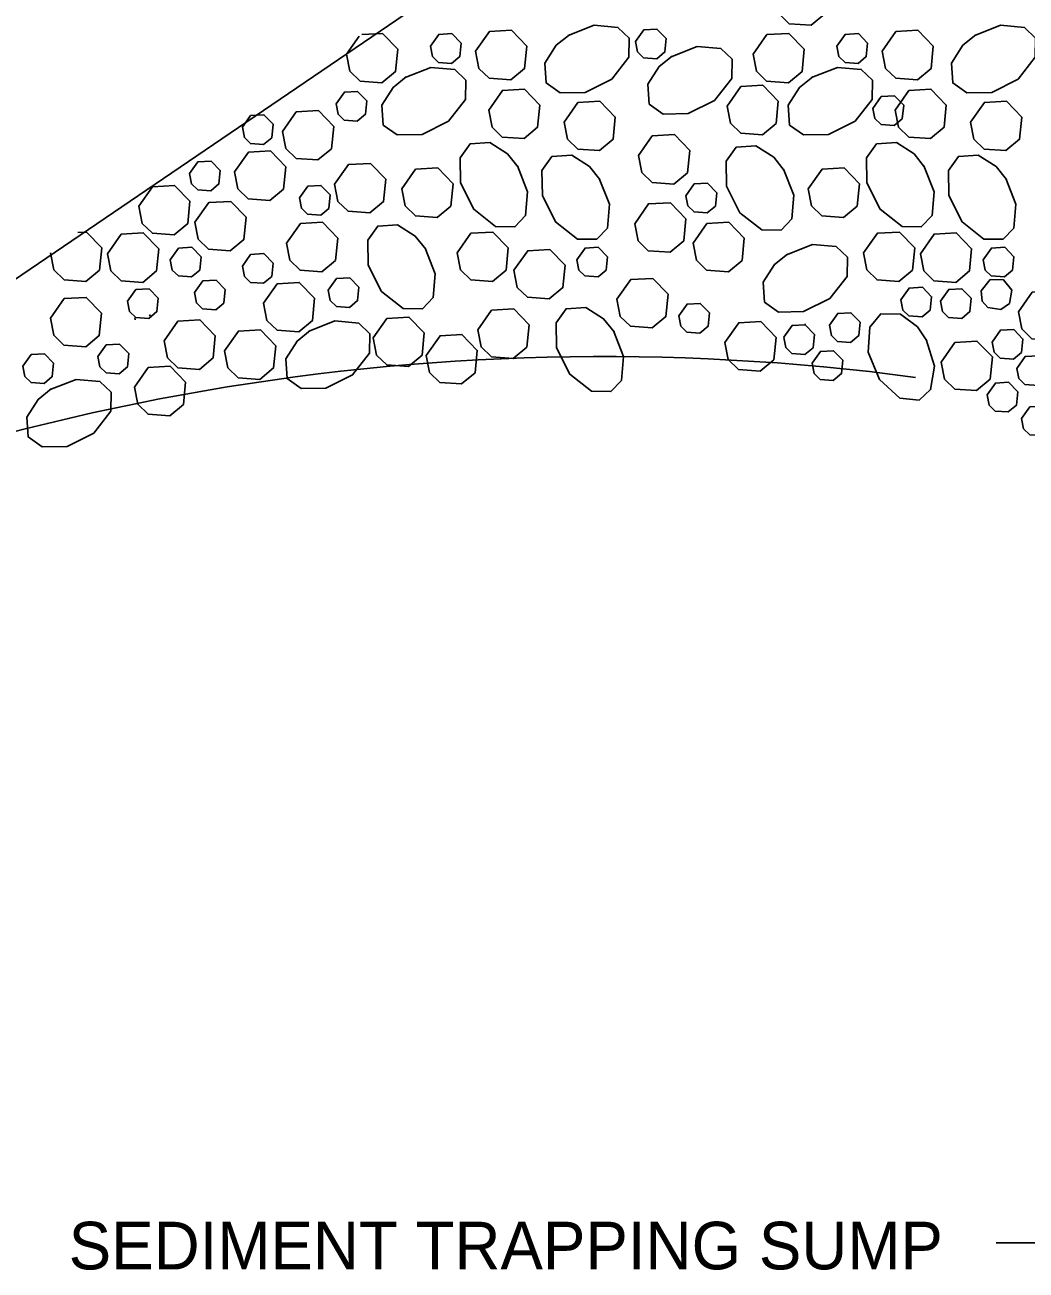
# Model space of a CAD drawing. Extents: x 6709491 to 6710959, y 1869789 to 1870763.
# Drawn here: x 6709570.8 to 6709696.9, y 1870141.6 to 1870298.5 of the extents above; entities that cross this region are included whole.
import ezdxf

# ---------------------------------------------------------------- set-up
doc = ezdxf.new("R2010")
doc.units = 0
for name, color, linetype in [('56 Stg 3 Anno', 7, 'Continuous'), ('57 Undefined', 7, 'Continuous'), ('60 Nongeo Data', 7, 'Continuous')]:
    doc.layers.add(name, color=color, linetype=linetype)

msp = doc.modelspace()

# ---------------------------------------------------------------- linework, layer by layer
at = {"layer": '56 Stg 3 Anno'}
msp.add_line((6709713.58, 1870145.05), (6709693.08, 1870145.05), dxfattribs=at)
at = {"layer": '60 Nongeo Data'}
msp.add_line((6709495.94, 1870216.26), (6709884.38, 1870481.01), dxfattribs=at)
for points in [[(6709665.33, 1870302.03), (6709667.07, 1870304.51), (6709669.85, 1870304.67), (6709671.78, 1870302.66), (6709671.5, 1870299.86), (6709669.79, 1870298.43), (6709667.04, 1870298.63), (6709665.75, 1870299.88), (6709665.34, 1870302.03)], [(6709613.19, 1870297.27), (6709615.8, 1870297.42), (6709617.74, 1870295.42), (6709617.46, 1870292.61), (6709615.74, 1870291.19), (6709613, 1870291.39), (6709611.71, 1870292.64), (6709611.29, 1870294.79)], [(6709611.29, 1870294.79), (6709612.88, 1870297.05)], [(6709612.88, 1870297.05), (6709612.88, 1870297.06)], [(6709621.84, 1870295.8), (6709622.89, 1870297.29), (6709624.55, 1870297.38), (6709625.71, 1870296.18), (6709625.54, 1870294.5), (6709624.51, 1870293.64), (6709622.87, 1870293.76), (6709622.09, 1870294.51), (6709621.84, 1870295.8)], [(6709627.54, 1870295.16), (6709629.28, 1870297.64), (6709632.06, 1870297.8), (6709633.99, 1870295.79), (6709633.71, 1870292.99), (6709631.99, 1870291.56), (6709629.25, 1870291.76), (6709627.96, 1870293.01), (6709627.54, 1870295.16)], [(6709639.21, 1870297.14), (6709642.47, 1870298.43), (6709645.46, 1870298.17), (6709646.88, 1870296.82), (6709646.83, 1870294.4), (6709644.68, 1870291.64), (6709641.34, 1870289.97), (6709638.2, 1870289.92), (6709636.44, 1870291.18), (6709636.27, 1870293.68), (6709637.7, 1870295.91), (6709639.35, 1870297.23)], [(6709647.67, 1870296.38), (6709648.71, 1870297.86), (6709650.38, 1870297.95), (6709651.54, 1870296.75), (6709651.37, 1870295.07), (6709650.34, 1870294.22), (6709648.7, 1870294.33), (6709647.92, 1870295.09), (6709647.67, 1870296.38)], [(6709662.48, 1870294.79), (6709664.22, 1870297.26), (6709667, 1870297.42), (6709668.93, 1870295.42), (6709668.65, 1870292.61), (6709666.93, 1870291.19), (6709664.19, 1870291.39), (6709662.9, 1870292.64), (6709662.48, 1870294.79)], [(6709673.03, 1870295.8), (6709674.08, 1870297.29), (6709675.74, 1870297.38), (6709676.9, 1870296.18), (6709676.74, 1870294.5), (6709675.71, 1870293.64), (6709674.06, 1870293.76), (6709673.29, 1870294.51), (6709673.04, 1870295.8)], [(6709678.74, 1870295.16), (6709680.47, 1870297.64), (6709683.25, 1870297.8), (6709685.18, 1870295.79), (6709684.9, 1870292.99), (6709683.19, 1870291.56), (6709680.45, 1870291.76), (6709679.15, 1870293.01), (6709678.74, 1870295.16)], [(6709690.41, 1870297.14), (6709693.66, 1870298.43), (6709696.65, 1870298.17), (6709698.07, 1870296.82), (6709698.03, 1870294.4), (6709695.87, 1870291.64), (6709692.54, 1870289.97), (6709689.4, 1870289.92), (6709687.63, 1870291.18), (6709687.46, 1870293.68), (6709688.9, 1870295.91), (6709690.54, 1870297.23)], [(6709652.18, 1870294.47), (6709655.43, 1870295.76), (6709658.42, 1870295.5), (6709659.84, 1870294.15), (6709659.79, 1870291.73), (6709657.64, 1870288.97), (6709654.31, 1870287.3), (6709651.17, 1870287.25), (6709649.4, 1870288.51), (6709649.23, 1870291.01), (6709650.67, 1870293.24), (6709652.31, 1870294.55)], [(6709618.66, 1870291.84), (6709621.91, 1870293.13), (6709624.9, 1870292.87), (6709626.32, 1870291.52), (6709626.28, 1870289.1), (6709624.12, 1870286.34), (6709620.79, 1870284.67), (6709617.65, 1870284.62), (6709615.88, 1870285.87), (6709615.71, 1870288.38), (6709617.15, 1870290.61), (6709618.79, 1870291.92)], [(6709669.85, 1870291.84), (6709673.11, 1870293.13), (6709676.1, 1870292.87), (6709677.52, 1870291.52), (6709677.47, 1870289.1), (6709675.32, 1870286.34), (6709671.98, 1870284.67), (6709668.84, 1870284.62), (6709667.08, 1870285.87), (6709666.91, 1870288.38), (6709668.34, 1870290.61), (6709669.99, 1870291.92)], [(6709659.21, 1870288.24), (6709660.95, 1870290.72), (6709663.73, 1870290.88), (6709665.66, 1870288.87), (6709665.38, 1870286.07), (6709663.66, 1870284.64), (6709660.92, 1870284.84), (6709659.63, 1870286.09), (6709659.21, 1870288.24)], [(6709609.96, 1870288.52), (6709611.01, 1870290.01), (6709612.67, 1870290.1), (6709613.83, 1870288.9), (6709613.66, 1870287.22), (6709612.63, 1870286.36), (6709610.99, 1870286.48), (6709610.21, 1870287.23), (6709609.96, 1870288.52)], [(6709629.18, 1870287.76), (6709630.92, 1870290.23), (6709633.69, 1870290.39), (6709635.62, 1870288.39), (6709635.35, 1870285.58), (6709633.63, 1870284.16), (6709630.89, 1870284.35), (6709629.6, 1870285.61), (6709629.18, 1870287.76)], [(6709677.58, 1870287.97), (6709678.62, 1870289.45), (6709680.29, 1870289.55), (6709681.45, 1870288.35), (6709681.28, 1870286.66), (6709680.25, 1870285.81), (6709678.61, 1870285.93), (6709677.83, 1870286.68), (6709677.58, 1870287.97)], [(6709680.37, 1870287.76), (6709682.11, 1870290.23), (6709684.89, 1870290.39), (6709686.82, 1870288.39), (6709686.54, 1870285.58), (6709684.82, 1870284.16), (6709682.08, 1870284.35), (6709680.79, 1870285.61), (6709680.37, 1870287.76)], [(6709603.21, 1870285.07), (6709604.95, 1870287.54), (6709607.73, 1870287.7), (6709609.66, 1870285.7), (6709609.38, 1870282.89), (6709607.67, 1870281.47), (6709604.92, 1870281.67), (6709603.63, 1870282.92), (6709603.22, 1870285.07)], [(6709638.69, 1870286.24), (6709640.43, 1870288.72), (6709643.2, 1870288.87), (6709645.13, 1870286.87), (6709644.85, 1870284.07), (6709643.14, 1870282.64), (6709640.4, 1870282.84), (6709639.11, 1870284.09), (6709638.69, 1870286.24)], [(6709689.88, 1870286.24), (6709691.62, 1870288.72), (6709694.4, 1870288.87), (6709696.33, 1870286.87), (6709696.05, 1870284.07), (6709694.33, 1870282.64), (6709691.59, 1870282.84), (6709690.3, 1870284.09), (6709689.88, 1870286.24)], [(6709598.16, 1870285.58), (6709599.2, 1870287.06), (6709600.87, 1870287.16), (6709602.03, 1870285.96), (6709601.86, 1870284.27), (6709600.83, 1870283.42), (6709599.18, 1870283.54), (6709598.41, 1870284.29), (6709598.16, 1870285.58)], [(6709648.05, 1870282.03), (6709649.79, 1870284.51), (6709652.57, 1870284.67), (6709654.5, 1870282.66), (6709654.22, 1870279.86), (6709652.51, 1870278.43), (6709649.77, 1870278.63), (6709648.48, 1870279.88), (6709648.06, 1870282.03)], [(6709632.8, 1870280.71), (6709634.09, 1870277.45), (6709633.83, 1870274.46), (6709632.48, 1870273.04), (6709630.05, 1870273.09), (6709627.3, 1870275.25), (6709625.63, 1870278.58), (6709625.58, 1870281.72), (6709626.83, 1870283.49), (6709629.33, 1870283.65), (6709631.57, 1870282.22), (6709632.88, 1870280.58)], [(6709666.31, 1870280.29), (6709667.6, 1870277.03), (6709667.35, 1870274.04), (6709666, 1870272.62), (6709663.57, 1870272.67), (6709660.81, 1870274.82), (6709659.15, 1870278.16), (6709659.09, 1870281.3), (6709660.35, 1870283.06), (6709662.85, 1870283.23), (6709665.09, 1870281.8), (6709666.4, 1870280.15)], [(6709683.99, 1870280.71), (6709685.28, 1870277.45), (6709685.02, 1870274.46), (6709683.67, 1870273.04), (6709681.25, 1870273.09), (6709678.49, 1870275.25), (6709676.83, 1870278.58), (6709676.77, 1870281.72), (6709678.03, 1870283.49), (6709680.53, 1870283.65), (6709682.76, 1870282.22), (6709684.07, 1870280.58)], [(6709591.5, 1870279.75), (6709592.54, 1870281.23), (6709594.21, 1870281.33), (6709595.37, 1870280.13), (6709595.2, 1870278.44), (6709594.17, 1870277.59), (6709592.53, 1870277.71), (6709591.75, 1870278.46), (6709591.5, 1870279.75)], [(6709597.18, 1870279.97), (6709598.92, 1870282.44), (6709601.7, 1870282.6), (6709603.63, 1870280.6), (6709603.35, 1870277.79), (6709601.63, 1870276.37), (6709598.89, 1870276.57), (6709597.6, 1870277.82), (6709597.18, 1870279.97)], [(6709643.11, 1870279.13), (6709644.4, 1870275.88), (6709644.14, 1870272.89), (6709642.79, 1870271.47), (6709640.37, 1870271.51), (6709637.61, 1870273.67), (6709635.94, 1870277), (6709635.89, 1870280.14), (6709637.14, 1870281.91), (6709639.65, 1870282.07), (6709641.88, 1870280.64), (6709643.19, 1870279)], [(6709694.3, 1870279.13), (6709695.59, 1870275.88), (6709695.34, 1870272.89), (6709693.98, 1870271.47), (6709691.56, 1870271.51), (6709688.8, 1870273.67), (6709687.14, 1870277), (6709687.08, 1870280.14), (6709688.34, 1870281.91), (6709690.84, 1870282.07), (6709693.08, 1870280.64), (6709694.39, 1870279)], [(6709609.77, 1870278.41), (6709611.51, 1870280.88), (6709614.29, 1870281.04), (6709616.22, 1870279.04), (6709615.94, 1870276.23), (6709614.22, 1870274.8), (6709611.48, 1870275), (6709610.19, 1870276.25), (6709609.77, 1870278.4)], [(6709618.24, 1870277.83), (6709619.98, 1870280.3), (6709622.76, 1870280.46), (6709624.69, 1870278.46), (6709624.41, 1870275.65), (6709622.7, 1870274.23), (6709619.96, 1870274.42), (6709618.67, 1870275.67), (6709618.25, 1870277.83)], [(6709669.44, 1870277.83), (6709671.18, 1870280.3), (6709673.95, 1870280.46), (6709675.89, 1870278.46), (6709675.61, 1870275.65), (6709673.89, 1870274.23), (6709671.15, 1870274.42), (6709669.86, 1870275.67), (6709669.44, 1870277.83)], [(6709585.11, 1870275.63), (6709586.85, 1870278.1), (6709589.62, 1870278.26), (6709591.56, 1870276.26), (6709591.28, 1870273.45), (6709589.56, 1870272.03), (6709586.82, 1870272.23), (6709585.53, 1870273.48), (6709585.11, 1870275.63)], [(6709605.35, 1870276.68), (6709606.39, 1870278.16), (6709608.06, 1870278.26), (6709609.21, 1870277.06), (6709609.05, 1870275.37), (6709608.02, 1870274.52), (6709606.37, 1870274.64), (6709605.6, 1870275.39), (6709605.35, 1870276.68)], [(6709654.03, 1870276.96), (6709655.08, 1870278.45), (6709656.74, 1870278.54), (6709657.9, 1870277.34), (6709657.73, 1870275.66), (6709656.7, 1870274.8), (6709655.06, 1870274.92), (6709654.28, 1870275.67), (6709654.03, 1870276.96)], [(6709592.19, 1870273.62), (6709593.93, 1870276.09), (6709596.7, 1870276.25), (6709598.63, 1870274.25), (6709598.35, 1870271.44), (6709596.64, 1870270.02), (6709593.9, 1870270.22), (6709592.61, 1870271.47), (6709592.19, 1870273.62)], [(6709647.57, 1870273.44), (6709649.31, 1870275.92), (6709652.08, 1870276.08), (6709654.01, 1870274.07), (6709653.74, 1870271.27), (6709652.02, 1870269.84), (6709649.28, 1870270.04), (6709647.99, 1870271.29), (6709647.57, 1870273.44)], [(6709603.72, 1870270.99), (6709605.46, 1870273.46), (6709608.24, 1870273.62), (6709610.17, 1870271.62), (6709609.89, 1870268.81), (6709608.18, 1870267.38), (6709605.43, 1870267.58), (6709604.14, 1870268.83), (6709603.73, 1870270.98)], [(6709654.92, 1870270.99), (6709656.66, 1870273.46), (6709659.43, 1870273.62), (6709661.37, 1870271.62), (6709661.09, 1870268.81), (6709659.37, 1870267.38), (6709656.63, 1870267.58), (6709655.34, 1870268.83), (6709654.92, 1870270.98)], [(6709577.42, 1870272.33), (6709578.53, 1870272.39), (6709580.46, 1870270.39), (6709580.18, 1870267.59), (6709578.46, 1870266.16), (6709575.72, 1870266.36), (6709574.43, 1870267.61), (6709574.01, 1870269.76)], [(6709581.17, 1870269.65), (6709582.91, 1870272.13), (6709585.68, 1870272.29), (6709587.62, 1870270.28), (6709587.34, 1870267.48), (6709585.62, 1870266.05), (6709582.88, 1870266.25), (6709581.59, 1870267.5), (6709581.17, 1870269.65)], [(6709621.17, 1870270.36), (6709622.46, 1870267.11), (6709622.2, 1870264.12), (6709620.85, 1870262.7), (6709618.43, 1870262.74), (6709615.67, 1870264.9), (6709614.01, 1870268.23), (6709613.95, 1870271.37), (6709615.21, 1870273.14), (6709617.71, 1870273.31), (6709619.94, 1870271.87), (6709621.25, 1870270.23)], [(6709625.21, 1870269.76), (6709626.94, 1870272.23), (6709629.72, 1870272.39), (6709631.65, 1870270.39), (6709631.37, 1870267.59), (6709629.66, 1870266.16), (6709626.92, 1870266.36), (6709625.63, 1870267.61), (6709625.21, 1870269.76)], [(6709676.4, 1870269.76), (6709678.14, 1870272.23), (6709680.92, 1870272.39), (6709682.85, 1870270.39), (6709682.57, 1870267.59), (6709680.85, 1870266.16), (6709678.11, 1870266.36), (6709676.82, 1870267.61), (6709676.4, 1870269.76)], [(6709683.55, 1870269.65), (6709685.29, 1870272.13), (6709688.07, 1870272.29), (6709690, 1870270.28), (6709689.72, 1870267.48), (6709688.01, 1870266.05), (6709685.26, 1870266.25), (6709683.97, 1870267.5), (6709683.56, 1870269.65)], [(6709589.08, 1870268.89), (6709590.12, 1870270.37), (6709591.79, 1870270.47), (6709592.95, 1870269.27), (6709592.78, 1870267.59), (6709591.75, 1870266.73), (6709590.11, 1870266.85), (6709589.33, 1870267.6), (6709589.08, 1870268.89)], [(6709640.28, 1870268.89), (6709641.32, 1870270.37), (6709642.99, 1870270.47), (6709644.14, 1870269.27), (6709643.98, 1870267.59), (6709642.95, 1870266.73), (6709641.3, 1870266.85), (6709640.53, 1870267.6), (6709640.28, 1870268.89)], [(6709666.7, 1870269.53), (6709669.95, 1870270.82), (6709672.94, 1870270.56), (6709674.36, 1870269.21), (6709674.32, 1870266.79), (6709672.16, 1870264.03), (6709668.83, 1870262.37), (6709665.69, 1870262.31), (6709663.92, 1870263.57), (6709663.75, 1870266.07), (6709665.19, 1870268.31), (6709666.83, 1870269.62)], [(6709691.47, 1870268.89), (6709692.51, 1870270.37), (6709694.18, 1870270.47), (6709695.34, 1870269.27), (6709695.17, 1870267.59), (6709694.14, 1870266.73), (6709692.49, 1870266.85), (6709691.72, 1870267.6), (6709691.47, 1870268.89)], [(6709598.16, 1870268.09), (6709599.2, 1870269.57), (6709600.87, 1870269.67), (6709602.03, 1870268.47), (6709601.86, 1870266.79), (6709600.83, 1870265.93), (6709599.18, 1870266.05), (6709598.41, 1870266.8), (6709598.16, 1870268.09)], [(6709632.36, 1870267.57), (6709634.1, 1870270.04), (6709636.88, 1870270.2), (6709638.81, 1870268.2), (6709638.53, 1870265.4), (6709636.81, 1870263.97), (6709634.07, 1870264.17), (6709632.78, 1870265.42), (6709632.36, 1870267.57)], [(6709592.13, 1870264.75), (6709593.17, 1870266.23), (6709594.84, 1870266.33), (6709595.99, 1870265.13), (6709595.83, 1870263.44), (6709594.8, 1870262.59), (6709593.15, 1870262.71), (6709592.38, 1870263.46), (6709592.13, 1870264.75)], [(6709600.81, 1870263.41), (6709602.55, 1870265.88), (6709605.32, 1870266.04), (6709607.26, 1870264.04), (6709606.98, 1870261.23), (6709605.26, 1870259.81), (6709602.52, 1870260.01), (6709601.23, 1870261.26), (6709600.81, 1870263.41)], [(6709608.97, 1870265.05), (6709610.02, 1870266.54), (6709611.68, 1870266.63), (6709612.84, 1870265.43), (6709612.67, 1870263.75), (6709611.64, 1870262.89), (6709610, 1870263.01), (6709609.22, 1870263.76), (6709608.97, 1870265.05)], [(6709645.33, 1870263.91), (6709647.07, 1870266.39), (6709649.85, 1870266.55), (6709651.78, 1870264.55), (6709651.5, 1870261.74), (6709649.78, 1870260.31), (6709647.04, 1870260.51), (6709645.75, 1870261.76), (6709645.33, 1870263.91)], [(6709691.2, 1870264.99), (6709692.36, 1870266.39), (6709694.03, 1870266.36), (6709695.09, 1870265.07), (6709694.79, 1870263.4), (6709693.7, 1870262.63), (6709692.07, 1870262.88), (6709691.35, 1870263.68), (6709691.2, 1870264.99)], [(6709573.98, 1870261.53), (6709575.72, 1870264), (6709578.49, 1870264.16), (6709580.42, 1870262.16), (6709580.14, 1870259.35), (6709578.43, 1870257.93), (6709575.69, 1870258.13), (6709574.4, 1870259.38), (6709573.98, 1870261.53)], [(6709583.7, 1870263.67), (6709584.74, 1870265.15), (6709586.41, 1870265.25), (6709587.57, 1870264.05), (6709587.4, 1870262.37), (6709586.37, 1870261.51), (6709584.72, 1870261.63), (6709583.95, 1870262.38), (6709583.7, 1870263.67)], [(6709681.09, 1870263.85), (6709682.13, 1870265.33), (6709683.8, 1870265.43), (6709684.96, 1870264.23), (6709684.79, 1870262.55), (6709683.76, 1870261.69), (6709682.11, 1870261.81), (6709681.34, 1870262.56), (6709681.09, 1870263.85)], [(6709686.08, 1870263.67), (6709687.13, 1870265.15), (6709688.79, 1870265.25), (6709689.95, 1870264.05), (6709689.79, 1870262.37), (6709688.76, 1870261.51), (6709687.11, 1870261.63), (6709686.34, 1870262.38), (6709686.09, 1870263.67)], [(6709695.9, 1870262.34), (6709697.64, 1870264.82), (6709700.41, 1870264.98), (6709702.34, 1870262.98), (6709702.06, 1870260.17), (6709700.35, 1870258.74), (6709697.61, 1870258.94), (6709696.32, 1870260.19), (6709695.9, 1870262.34)], [(6709627.81, 1870260.07), (6709629.55, 1870262.54), (6709632.33, 1870262.7), (6709634.26, 1870260.7), (6709633.98, 1870257.9), (6709632.26, 1870256.47), (6709629.52, 1870256.67), (6709628.23, 1870257.92), (6709627.81, 1870260.07)], [(6709644.89, 1870259.94), (6709646.18, 1870256.69), (6709645.92, 1870253.7), (6709644.57, 1870252.28), (6709642.14, 1870252.33), (6709639.39, 1870254.48), (6709637.72, 1870257.81), (6709637.67, 1870260.95), (6709638.92, 1870262.72), (6709641.42, 1870262.89), (6709643.66, 1870261.46), (6709644.97, 1870259.81)], [(6709653.12, 1870261.82), (6709654.16, 1870263.31), (6709655.83, 1870263.4), (6709656.99, 1870262.2), (6709656.82, 1870260.52), (6709655.79, 1870259.66), (6709654.14, 1870259.78), (6709653.37, 1870260.53), (6709653.12, 1870261.82)], [(6709584.66, 1870261.33), (6709584.61, 1870261.59)], [(6709586.44, 1870261.83), (6709586.57, 1870261.94)], [(6709588.3, 1870258.69), (6709590.04, 1870261.17), (6709592.82, 1870261.33), (6709594.75, 1870259.32), (6709594.47, 1870256.52), (6709592.75, 1870255.09), (6709590.01, 1870255.29), (6709588.72, 1870256.54), (6709588.3, 1870258.69)], [(6709606.56, 1870259.89), (6709609.82, 1870261.18), (6709612.81, 1870260.92), (6709614.23, 1870259.57), (6709614.18, 1870257.14), (6709612.03, 1870254.38), (6709608.69, 1870252.72), (6709605.55, 1870252.66), (6709603.79, 1870253.92), (6709603.62, 1870256.42), (6709605.05, 1870258.66), (6709606.7, 1870259.97)], [(6709614.63, 1870259.04), (6709616.36, 1870261.51), (6709619.14, 1870261.67), (6709621.07, 1870259.67), (6709620.79, 1870256.87), (6709619.08, 1870255.44), (6709616.34, 1870255.64), (6709615.05, 1870256.89), (6709614.63, 1870259.04)], [(6709658.93, 1870258.47), (6709660.67, 1870260.95), (6709663.45, 1870261.11), (6709665.38, 1870259.1), (6709665.1, 1870256.3), (6709663.38, 1870254.87), (6709660.64, 1870255.07), (6709659.35, 1870256.32), (6709658.93, 1870258.47)], [(6709669.05, 1870260.78), (6709669.04, 1870260.82)], [(6709672.1, 1870260.64), (6709673.14, 1870262.13), (6709674.81, 1870262.22), (6709675.97, 1870261.02), (6709675.8, 1870259.34), (6709674.77, 1870258.48), (6709673.13, 1870258.6), (6709672.35, 1870259.35), (6709672.1, 1870260.64)], [(6709684.3, 1870258.84), (6709685.33, 1870255.5), (6709684.84, 1870252.54), (6709683.39, 1870251.22), (6709680.97, 1870251.46), (6709678.39, 1870253.82), (6709676.99, 1870257.27), (6709677.18, 1870260.41), (6709678.57, 1870262.07), (6709681.07, 1870262.05), (6709683.19, 1870260.44), (6709684.37, 1870258.7)], [(6709595.92, 1870257.43), (6709597.66, 1870259.9), (6709600.44, 1870260.06), (6709602.37, 1870258.06), (6709602.09, 1870255.26), (6709600.37, 1870253.83), (6709597.63, 1870254.03), (6709596.34, 1870255.28), (6709595.92, 1870257.43)], [(6709621.31, 1870256.85), (6709623.05, 1870259.32), (6709625.82, 1870259.48), (6709627.75, 1870257.48), (6709627.47, 1870254.67), (6709625.76, 1870253.25), (6709623.02, 1870253.44), (6709621.73, 1870254.7), (6709621.31, 1870256.85)], [(6709666.34, 1870259.13), (6709667.39, 1870260.61), (6709669.05, 1870260.71), (6709670.21, 1870259.5), (6709670.05, 1870257.82), (6709669.02, 1870256.96), (6709667.37, 1870257.08), (6709666.6, 1870257.83), (6709666.35, 1870259.12)], [(6709692.6, 1870258.53), (6709693.64, 1870260.02), (6709695.31, 1870260.11), (6709696.47, 1870258.91), (6709696.3, 1870257.23), (6709695.27, 1870256.37), (6709693.62, 1870256.49), (6709692.85, 1870257.24), (6709692.6, 1870258.53)], [(6709579.97, 1870256.7), (6709581.01, 1870258.18), (6709582.68, 1870258.28), (6709583.84, 1870257.08), (6709583.67, 1870255.39), (6709582.64, 1870254.54), (6709581, 1870254.66), (6709580.22, 1870255.41), (6709579.97, 1870256.7)], [(6709686.17, 1870256.01), (6709687.91, 1870258.49), (6709690.68, 1870258.65), (6709692.62, 1870256.65), (6709692.34, 1870253.84), (6709690.62, 1870252.41), (6709687.88, 1870252.61), (6709686.59, 1870253.86), (6709686.17, 1870256.01)], [(6709570.52, 1870255.47), (6709571.56, 1870256.95), (6709573.23, 1870257.05), (6709574.38, 1870255.85), (6709574.22, 1870254.17), (6709573.19, 1870253.31), (6709571.54, 1870253.43), (6709570.77, 1870254.18), (6709570.52, 1870255.47)], [(6709669.92, 1870255.86), (6709670.96, 1870257.35), (6709672.63, 1870257.44), (6709673.79, 1870256.24), (6709673.62, 1870254.56), (6709672.59, 1870253.7), (6709670.95, 1870253.82), (6709670.17, 1870254.57), (6709669.92, 1870255.86)], [(6709695.71, 1870255.21), (6709696.75, 1870256.7), (6709698.42, 1870256.79), (6709699.58, 1870255.59), (6709699.41, 1870253.91), (6709698.38, 1870253.05), (6709696.73, 1870253.17), (6709695.96, 1870253.92), (6709695.71, 1870255.21)], [(6709584.57, 1870252.84), (6709586.3, 1870255.31), (6709589.08, 1870255.47), (6709591.01, 1870253.47), (6709590.73, 1870250.66), (6709589.02, 1870249.24), (6709586.28, 1870249.44), (6709584.99, 1870250.69), (6709584.57, 1870252.84)], [(6709573.96, 1870252.54), (6709577.22, 1870253.83), (6709580.21, 1870253.57), (6709581.63, 1870252.22), (6709581.58, 1870249.8), (6709579.43, 1870247.04), (6709576.09, 1870245.37), (6709572.95, 1870245.32), (6709571.18, 1870246.57), (6709571.02, 1870249.08), (6709572.45, 1870251.31), (6709574.09, 1870252.62)], [(6709691.96, 1870251.88), (6709693, 1870253.36), (6709694.67, 1870253.46), (6709695.83, 1870252.25), (6709695.66, 1870250.57), (6709694.63, 1870249.72), (6709692.99, 1870249.84), (6709692.21, 1870250.59), (6709691.96, 1870251.88)], [(6709696.3, 1870248.9), (6709697.34, 1870250.38), (6709699.01, 1870250.47), (6709700.17, 1870249.27), (6709700, 1870247.59), (6709698.97, 1870246.74), (6709697.32, 1870246.85), (6709696.55, 1870247.6), (6709696.3, 1870248.9)]]:
    msp.add_lwpolyline(points, dxfattribs=at)
msp.add_arc((6709643.67, 1869960.83), 295.87, 82.3714, 118.3095, dxfattribs=at)

# ---------------------------------------------------------------- texts
at = {"layer": '57 Undefined'}
msp.add_text('SEDIMENT TRAPPING SUMP', height=6, dxfattribs=at).set_placement((6709576.28, 1870141.7))

doc.saveas('drawing.dxf')
